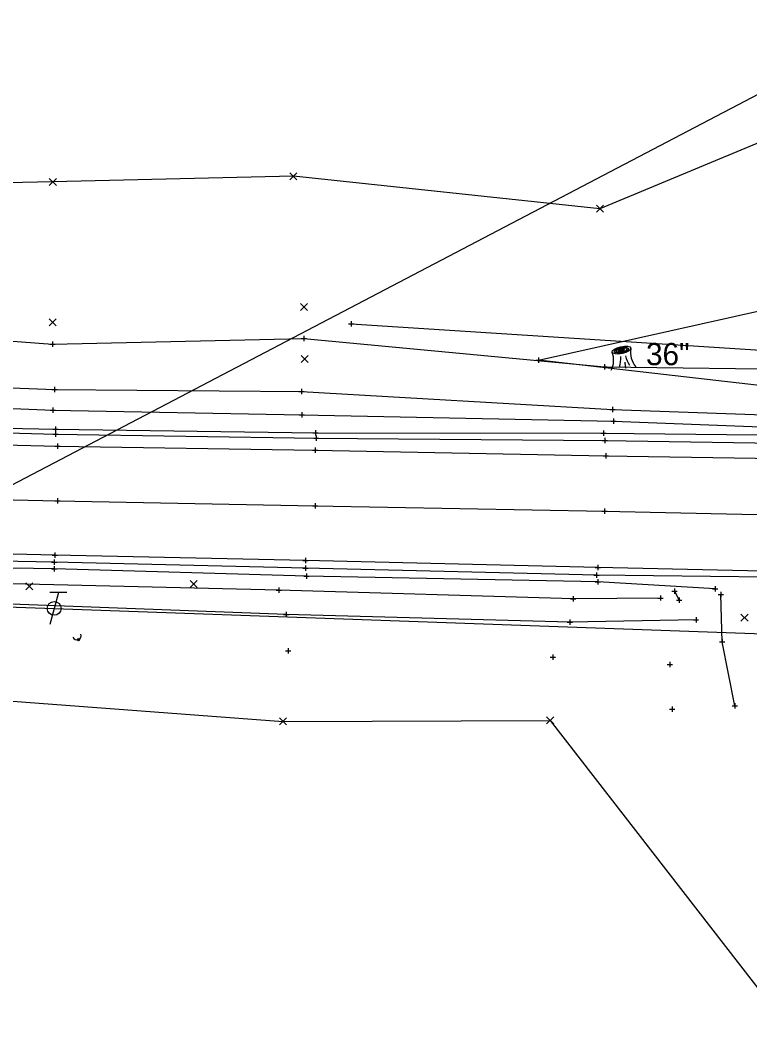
# Model space of a CAD drawing. Extents: x 2005176 to 2005823, y 572472 to 572942.
# Drawn here: x 2005315.2 to 2005452.2, y 572515.6 to 572703.5 of the extents above; entities that cross this region are included whole.
import ezdxf

# ---------------------------------------------------------------- set-up
doc = ezdxf.new("R2010")
doc.units = 0
for name, color, linetype in [('DV_X_Lot_Line', 7, 'Continuous'), ('GE_X_Alignment_1000_Bearings', 7, 'Continuous'), ('GE_X_Alignment_1000_Cardinal_Points', 7, 'Continuous'), ('GE_X_Alignment_100_Bearings', 7, 'Continuous'), ('GE_X_Alignment_100_Cardinal_Points', 7, 'Continuous'), ('GE_X_Alignment_100_Curve_Data', 7, 'Continuous'), ('GE_X_Alignment_100_Distances', 7, 'Continuous'), ('GE_X_Alignment_100_Stations', 7, 'Continuous'), ('GE_X_Alignment_500_Bearings', 7, 'Continuous'), ('GE_X_Alignment_500_Cardinal_Points', 7, 'Continuous'), ('GE_X_Alignment_500_Distances', 7, 'Continuous'), ('SC_Scratch1', 7, 'Continuous'), ('SC_Scratch10', 7, 'Continuous'), ('SC_Scratch8', 7, 'Continuous'), ('SV_P_Mon_Cells_Set', 7, 'Continuous'), ('SV_X_Random_Point', 7, 'Continuous'), ('SV_X_Shot_Marker', 7, 'Continuous'), ('SV_X_Terrain_Boundary', 7, 'Continuous'), ('UT_X_Overhead_Electric', 7, 'Continuous'), ('UT_X_Overhead_Telecom', 7, 'Continuous'), ('VG_X_Text', 7, 'Continuous')]:
    doc.layers.add(name, color=color, linetype=linetype)

msp = doc.modelspace()

# ---------------------------------------------------------------- linework, layer by layer
at = {"layer": 'DV_X_Lot_Line'}
msp.add_circle((2005326.15, 572587.14), 0.2, dxfattribs=at)
msp.add_arc((2005325.87, 572587.89), 0.8, 200, 20, dxfattribs=at)
at = {"layer": 'GE_X_Alignment_1000_Bearings'}
msp.add_lwpolyline([(2005377.36, 572646.47), (2005740.51, 572623.1)], dxfattribs=at)
at = {"layer": 'GE_X_Alignment_1000_Cardinal_Points'}
msp.add_lwpolyline([(2005589.36, 572669.58), (2005577.83, 572653.68), (2005542.16, 572637.38), (2005475.27, 572632.41), (2005412.5, 572639.63), (2005455.37, 572649.17), (2005453.82, 572664.21)], dxfattribs=at)
at = {"layer": 'GE_X_Alignment_100_Bearings'}
for points in [[(2005220.7, 572626.42), (2005272.19, 572624.71), (2005322.24, 572623.5), (2005370.59, 572622.7), (2005425.14, 572621.65), (2005477.36, 572620.84), (2005525.07, 572619.6), (2005576.7, 572617.86), (2005628.14, 572615.99), (2005678.39, 572614.09), (2005728.23, 572612.03), (2005777.04, 572611.02), (2005819.95, 572609.99)], [(2005818.64, 572588.97), (2005775.2, 572590.4), (2005728.29, 572591.88), (2005676.68, 572593.61), (2005626.55, 572595.19), (2005577.83, 572596.72), (2005526.97, 572598.44), (2005477.01, 572599.53), (2005423.67, 572600.7), (2005368.75, 572601.99), (2005321.74, 572602.99), (2005266.72, 572604.35), (2005220.03, 572605.66)]]:
    msp.add_lwpolyline(points, dxfattribs=at)
at = {"layer": 'GE_X_Alignment_100_Cardinal_Points'}
msp.add_lwpolyline([(2005220.5, 572615.99), (2005272.51, 572614.37), (2005322.2, 572613.2), (2005370.62, 572612.29), (2005424.94, 572611.27), (2005476.5, 572610.17), (2005524.32, 572608.79), (2005576.49, 572607.4), (2005627.69, 572605.77), (2005677.11, 572603.68), (2005728.03, 572601.92), (2005776.18, 572600.5), (2005820.14, 572599.28)], dxfattribs=at)
at = {"layer": 'GE_X_Alignment_100_Curve_Data'}
msp.add_lwpolyline([(2005449.4, 572574.75), (2005447.03, 572586.75), (2005446.73, 572595.6)], dxfattribs=at)
at = {"layer": 'GE_X_Alignment_100_Distances'}
for points in [[(2005220.68, 572626.38), (2005272.19, 572624.71), (2005322.24, 572623.5), (2005370.59, 572622.7), (2005425.14, 572621.65), (2005477.36, 572620.84), (2005525.07, 572619.6), (2005576.7, 572617.86), (2005628.14, 572615.99), (2005678.39, 572614.09), (2005728.23, 572612.03), (2005777.04, 572611.02), (2005820.02, 572609.9)], [(2005818.7, 572589.05), (2005775.2, 572590.4), (2005728.29, 572591.88), (2005676.68, 572593.61), (2005626.55, 572595.19), (2005577.83, 572596.72), (2005526.97, 572598.44), (2005477.01, 572599.53), (2005423.67, 572600.7), (2005368.75, 572601.99), (2005321.74, 572602.99), (2005266.72, 572604.35), (2005220.06, 572605.65)]]:
    msp.add_lwpolyline(points, dxfattribs=at)
at = {"layer": 'GE_X_Alignment_100_Stations'}
for points in [[(2005222.43, 572636.47), (2005271.73, 572636.06), (2005321.63, 572634.11), (2005368.05, 572633.72), (2005426.44, 572630.35), (2005456.6, 572629.27), (2005476.49, 572629.52), (2005493.02, 572629.48), (2005502.46, 572637.33)], [(2005435.44, 572594.97), (2005419.01, 572594.84), (2005363.8, 572596.44), (2005313.6, 572597.65), (2005274.17, 572598.2), (2005257.36, 572598.58), (2005234.71, 572598.81)]]:
    msp.add_lwpolyline(points, dxfattribs=at)
at = {"layer": 'GE_X_Alignment_500_Bearings'}
for points in [[(2005221.46, 572633.88), (2005271.77, 572632.29), (2005321.33, 572630.21), (2005368.11, 572629.36), (2005426.58, 572628.14), (2005455.88, 572627.02), (2005475.7, 572627.77)], [(2005438.04, 572596.23), (2005438.95, 572594.56)]]:
    msp.add_lwpolyline(points, dxfattribs=at)
at = {"layer": 'GE_X_Alignment_500_Cardinal_Points'}
for points in [[(2005223.7, 572649.48), (2005272.16, 572646.31), (2005321.29, 572642.61), (2005368.45, 572643.7), (2005424.94, 572638.4), (2005464.26, 572637.84), (2005477.31, 572636.75), (2005486.33, 572634.29), (2005489.17, 572649.33), (2005492.03, 572660.48), (2005500.98, 572662.63), (2005517.14, 572685.76), (2005532.69, 572703.48)], [(2005442.09, 572590.88), (2005418.43, 572590.46), (2005365.12, 572591.87), (2005313.53, 572593.79), (2005275.04, 572595.23), (2005256.78, 572594), (2005241.01, 572592.26)]]:
    msp.add_lwpolyline(points, dxfattribs=at)
at = {"layer": 'GE_X_Alignment_500_Distances'}
msp.add_lwpolyline([(2005220.4, 572616.04), (2005272.51, 572614.37), (2005322.2, 572613.2), (2005370.62, 572612.29), (2005424.94, 572611.27), (2005476.5, 572610.17), (2005524.32, 572608.79), (2005576.49, 572607.4), (2005627.69, 572605.77), (2005677.11, 572603.68), (2005728.03, 572601.92), (2005776.18, 572600.5), (2005820.14, 572599.26)], dxfattribs=at)
at = {"layer": 'SC_Scratch1'}
for p, q in [((2005322.4, 572596.02), (2005320.79, 572590.02)), ((2005324, 572596.02), (2005320.8, 572596.02))]:
    msp.add_line(p, q, dxfattribs=at)
msp.add_circle((2005321.6, 572593.02), 1.3, dxfattribs=at)
at = {"layer": 'SC_Scratch10'}
for points in [[(2005220.88, 572629.15), (2005272.14, 572627.64), (2005321.83, 572626.68), (2005370.65, 572626), (2005424.7, 572625.92), (2005476.69, 572625.33), (2005525.49, 572622.56), (2005576.48, 572620.99), (2005628.3, 572618.68), (2005678.32, 572615.98), (2005728.35, 572614.83)], [(2005445.69, 572596.69), (2005423.63, 572598.01), (2005368.95, 572599.06), (2005321.59, 572600.44), (2005267.14, 572601.3), (2005220.21, 572602.17)]]:
    msp.add_lwpolyline(points, dxfattribs=at)
at = {"layer": 'SC_Scratch8'}
for points in [[(2005220.9, 572628.72), (2005272.16, 572627.13), (2005321.83, 572625.74), (2005370.81, 572625), (2005424.98, 572624.56), (2005477.31, 572623.7), (2005525.21, 572621.63), (2005576.56, 572620.01), (2005628.24, 572617.89), (2005678.25, 572615.23), (2005728.27, 572613.25), (2005777.12, 572612.24), (2005820.02, 572611.5)], [(2005818.66, 572586.64), (2005775.01, 572588.28), (2005728.16, 572589.79), (2005676.75, 572591.58), (2005626.73, 572593.57), (2005577.92, 572595.76), (2005527.42, 572597.32), (2005476.91, 572598.65), (2005423.43, 572599.27), (2005368.77, 572600.6), (2005321.59, 572601.67), (2005267.03, 572602.73), (2005220.03, 572603.93)]]:
    msp.add_lwpolyline(points, dxfattribs=at)
at = {"layer": 'SV_P_Mon_Cells_Set'}
for p, q in [((2005376.86, 572646.47), (2005377.86, 572646.47)), ((2005377.36, 572646.97), (2005377.36, 572645.97)), ((2005377.36, 572646.47), (2005377.36, 572646.47)), ((2005368.45, 572644.2), (2005368.45, 572643.2)), ((2005320.79, 572642.61), (2005321.79, 572642.61)), ((2005321.29, 572643.11), (2005321.29, 572642.11)), ((2005321.29, 572642.61), (2005321.29, 572642.61)), ((2005367.95, 572643.7), (2005368.95, 572643.7)), ((2005368.45, 572643.7), (2005368.45, 572643.7)), ((2005412, 572639.63), (2005413, 572639.63)), ((2005412.5, 572640.13), (2005412.5, 572639.13)), ((2005412.5, 572639.63), (2005412.5, 572639.63)), ((2005424.44, 572638.4), (2005425.44, 572638.4)), ((2005424.94, 572638.9), (2005424.94, 572637.9)), ((2005424.94, 572638.4), (2005424.94, 572638.4)), ((2005321.63, 572634.61), (2005321.63, 572633.61)), ((2005321.13, 572634.11), (2005322.13, 572634.11)), ((2005321.63, 572634.11), (2005321.63, 572634.11)), ((2005367.55, 572633.72), (2005368.55, 572633.72)), ((2005368.05, 572634.22), (2005368.05, 572633.22)), ((2005368.05, 572633.72), (2005368.05, 572633.72)), ((2005426.44, 572630.85), (2005426.44, 572629.85)), ((2005320.83, 572630.21), (2005321.83, 572630.21)), ((2005321.33, 572630.71), (2005321.33, 572629.71)), ((2005321.33, 572630.21), (2005321.33, 572630.21)), ((2005367.61, 572629.36), (2005368.61, 572629.36)), ((2005368.11, 572629.86), (2005368.11, 572628.86)), ((2005368.11, 572629.36), (2005368.11, 572629.36)), ((2005425.94, 572630.35), (2005426.94, 572630.35)), ((2005426.44, 572630.35), (2005426.44, 572630.35)), ((2005321.83, 572627.18), (2005321.83, 572626.18)), ((2005426.08, 572628.14), (2005427.08, 572628.14)), ((2005426.58, 572628.64), (2005426.58, 572627.64)), ((2005426.58, 572628.14), (2005426.58, 572628.14)), ((2005321.33, 572626.68), (2005322.33, 572626.68)), ((2005321.33, 572625.74), (2005322.33, 572625.74)), ((2005321.83, 572626.68), (2005321.83, 572626.68)), ((2005321.83, 572626.24), (2005321.83, 572625.24)), ((2005321.83, 572625.74), (2005321.83, 572625.74)), ((2005370.15, 572626), (2005371.15, 572626)), ((2005370.65, 572626.5), (2005370.65, 572625.5)), ((2005370.65, 572626), (2005370.65, 572626)), ((2005370.81, 572625.5), (2005370.81, 572624.5)), ((2005424.2, 572625.92), (2005425.2, 572625.92)), ((2005424.7, 572626.42), (2005424.7, 572625.42)), ((2005424.7, 572625.92), (2005424.7, 572625.92)), ((2005321.74, 572623.5), (2005322.74, 572623.5)), ((2005321.74, 572623.5), (2005322.74, 572623.5)), ((2005322.24, 572624), (2005322.24, 572623)), ((2005322.24, 572624), (2005322.24, 572623)), ((2005322.24, 572623.5), (2005322.24, 572623.5)), ((2005322.24, 572623.5), (2005322.24, 572623.5)), ((2005370.31, 572625), (2005371.31, 572625)), ((2005370.81, 572625), (2005370.81, 572625)), ((2005424.48, 572624.56), (2005425.48, 572624.56)), ((2005424.98, 572625.06), (2005424.98, 572624.06)), ((2005424.98, 572624.56), (2005424.98, 572624.56)), ((2005370.09, 572622.7), (2005371.09, 572622.7)), ((2005370.09, 572622.7), (2005371.09, 572622.7)), ((2005370.59, 572623.2), (2005370.59, 572622.2)), ((2005370.59, 572623.2), (2005370.59, 572622.2)), ((2005370.59, 572622.7), (2005370.59, 572622.7)), ((2005370.59, 572622.7), (2005370.59, 572622.7)), ((2005424.64, 572621.65), (2005425.64, 572621.65)), ((2005424.64, 572621.65), (2005425.64, 572621.65)), ((2005425.14, 572622.15), (2005425.14, 572621.15)), ((2005425.14, 572622.15), (2005425.14, 572621.15)), ((2005425.14, 572621.65), (2005425.14, 572621.65)), ((2005425.14, 572621.65), (2005425.14, 572621.65)), ((2005321.7, 572613.2), (2005322.7, 572613.2)), ((2005321.7, 572613.2), (2005322.7, 572613.2)), ((2005322.2, 572613.7), (2005322.2, 572612.7)), ((2005322.2, 572613.7), (2005322.2, 572612.7)), ((2005322.2, 572613.2), (2005322.2, 572613.2)), ((2005322.2, 572613.2), (2005322.2, 572613.2)), ((2005370.12, 572612.29), (2005371.12, 572612.29)), ((2005370.12, 572612.29), (2005371.12, 572612.29)), ((2005370.62, 572612.79), (2005370.62, 572611.79)), ((2005370.62, 572612.79), (2005370.62, 572611.79)), ((2005370.62, 572612.29), (2005370.62, 572612.29)), ((2005370.62, 572612.29), (2005370.62, 572612.29)), ((2005424.44, 572611.27), (2005425.44, 572611.27)), ((2005424.44, 572611.27), (2005425.44, 572611.27)), ((2005424.94, 572611.77), (2005424.94, 572610.77)), ((2005424.94, 572611.77), (2005424.94, 572610.77)), ((2005424.94, 572611.27), (2005424.94, 572611.27)), ((2005424.94, 572611.27), (2005424.94, 572611.27)), ((2005321.24, 572602.99), (2005322.24, 572602.99)), ((2005321.24, 572602.99), (2005322.24, 572602.99)), ((2005321.74, 572603.49), (2005321.74, 572602.49)), ((2005321.74, 572603.49), (2005321.74, 572602.49)), ((2005321.74, 572602.99), (2005321.74, 572602.99)), ((2005321.74, 572602.99), (2005321.74, 572602.99)), ((2005321.09, 572601.67), (2005322.09, 572601.67)), ((2005321.59, 572602.17), (2005321.59, 572601.17)), ((2005321.59, 572601.67), (2005321.59, 572601.67)), ((2005321.59, 572600.94), (2005321.59, 572599.94)), ((2005368.25, 572601.99), (2005369.25, 572601.99)), ((2005368.25, 572601.99), (2005369.25, 572601.99)), ((2005368.75, 572602.49), (2005368.75, 572601.49)), ((2005368.75, 572602.49), (2005368.75, 572601.49)), ((2005368.75, 572601.99), (2005368.75, 572601.99)), ((2005368.75, 572601.99), (2005368.75, 572601.99)), ((2005368.77, 572601.1), (2005368.77, 572600.1)), ((2005423.67, 572601.2), (2005423.67, 572600.2)), ((2005423.67, 572601.2), (2005423.67, 572600.2)), ((2005321.09, 572600.44), (2005322.09, 572600.44)), ((2005321.59, 572600.44), (2005321.59, 572600.44)), ((2005368.27, 572600.6), (2005369.27, 572600.6)), ((2005368.45, 572599.06), (2005369.45, 572599.06)), ((2005368.77, 572600.6), (2005368.77, 572600.6)), ((2005368.95, 572599.56), (2005368.95, 572598.56)), ((2005368.95, 572599.06), (2005368.95, 572599.06)), ((2005422.93, 572599.27), (2005423.93, 572599.27)), ((2005423.17, 572600.7), (2005424.17, 572600.7)), ((2005423.17, 572600.7), (2005424.17, 572600.7)), ((2005423.43, 572599.77), (2005423.43, 572598.77)), ((2005423.43, 572599.27), (2005423.43, 572599.27)), ((2005423.67, 572600.7), (2005423.67, 572600.7)), ((2005423.67, 572600.7), (2005423.67, 572600.7)), ((2005423.13, 572598.01), (2005424.13, 572598.01)), ((2005423.63, 572598.51), (2005423.63, 572597.51)), ((2005423.63, 572598.01), (2005423.63, 572598.01)), ((2005445.69, 572597.19), (2005445.69, 572596.19)), ((2005363.3, 572596.44), (2005364.3, 572596.44)), ((2005363.8, 572596.94), (2005363.8, 572595.94)), ((2005363.8, 572596.44), (2005363.8, 572596.44)), ((2005419.01, 572595.34), (2005419.01, 572594.34)), ((2005435.44, 572595.47), (2005435.44, 572594.47)), ((2005437.54, 572596.23), (2005438.54, 572596.23)), ((2005438.04, 572596.73), (2005438.04, 572595.73)), ((2005438.04, 572596.23), (2005438.04, 572596.23)), ((2005445.19, 572596.69), (2005446.19, 572596.69)), ((2005445.69, 572596.69), (2005445.69, 572596.69)), ((2005446.23, 572595.6), (2005447.23, 572595.6)), ((2005446.73, 572596.1), (2005446.73, 572595.1)), ((2005446.73, 572595.6), (2005446.73, 572595.6)), ((2005418.51, 572594.84), (2005419.51, 572594.84)), ((2005419.01, 572594.84), (2005419.01, 572594.84)), ((2005434.94, 572594.97), (2005435.94, 572594.97)), ((2005435.44, 572594.97), (2005435.44, 572594.97)), ((2005438.45, 572594.56), (2005439.45, 572594.56)), ((2005438.95, 572595.06), (2005438.95, 572594.06)), ((2005438.95, 572594.56), (2005438.95, 572594.56)), ((2005364.62, 572591.87), (2005365.62, 572591.87)), ((2005365.12, 572592.37), (2005365.12, 572591.37)), ((2005365.12, 572591.87), (2005365.12, 572591.87)), ((2005442.09, 572591.38), (2005442.09, 572590.38)), ((2005417.93, 572590.46), (2005418.93, 572590.46)), ((2005418.43, 572590.96), (2005418.43, 572589.96)), ((2005418.43, 572590.46), (2005418.43, 572590.46)), ((2005441.59, 572590.88), (2005442.59, 572590.88)), ((2005442.09, 572590.88), (2005442.09, 572590.88)), ((2005446.53, 572586.75), (2005447.53, 572586.75)), ((2005447.03, 572587.25), (2005447.03, 572586.25)), ((2005447.03, 572586.75), (2005447.03, 572586.75)), ((2005365.04, 572585.07), (2005366.04, 572585.07)), ((2005365.54, 572585.57), (2005365.54, 572584.57)), ((2005365.54, 572585.07), (2005365.54, 572585.07)), ((2005414.72, 572583.89), (2005415.72, 572583.89)), ((2005415.22, 572584.39), (2005415.22, 572583.39)), ((2005415.22, 572583.89), (2005415.22, 572583.89)), ((2005436.65, 572582.46), (2005437.65, 572582.46)), ((2005437.15, 572582.96), (2005437.15, 572581.96)), ((2005437.15, 572582.46), (2005437.15, 572582.46)), ((2005437.62, 572574.57), (2005437.62, 572573.57)), ((2005448.9, 572574.75), (2005449.9, 572574.75)), ((2005449.4, 572575.25), (2005449.4, 572574.25)), ((2005449.4, 572574.75), (2005449.4, 572574.75)), ((2005437.12, 572574.07), (2005438.12, 572574.07)), ((2005437.62, 572574.07), (2005437.62, 572574.07))]:
    msp.add_line(p, q, dxfattribs=at)
at = {"layer": 'SV_X_Random_Point'}
for p, q in [((2005365.84, 572673.48), (2005367.18, 572674.82)), ((2005365.84, 572674.82), (2005367.18, 572673.48)), ((2005320.67, 572672.42), (2005322, 572673.76)), ((2005320.67, 572673.76), (2005322, 572672.42)), ((2005423.39, 572667.4), (2005424.72, 572668.73)), ((2005423.39, 572668.73), (2005424.72, 572667.4)), ((2005367.85, 572648.93), (2005369.18, 572650.26)), ((2005367.85, 572650.26), (2005369.18, 572648.93)), ((2005320.63, 572646.07), (2005321.97, 572647.4)), ((2005320.63, 572647.4), (2005321.97, 572646.07)), ((2005367.97, 572639.18), (2005369.3, 572640.52)), ((2005367.97, 572640.52), (2005369.3, 572639.18)), ((2005316.26, 572596.5), (2005317.59, 572597.83)), ((2005316.26, 572597.83), (2005317.59, 572596.5)), ((2005347.13, 572596.94), (2005348.46, 572598.28)), ((2005347.13, 572598.28), (2005348.46, 572596.94)), ((2005450.53, 572590.61), (2005451.86, 572591.95)), ((2005450.53, 572591.95), (2005451.86, 572590.61)), ((2005414.04, 572571.33), (2005415.37, 572572.66)), ((2005414.04, 572572.66), (2005415.37, 572571.33)), ((2005363.9, 572571.14), (2005365.24, 572572.48)), ((2005363.9, 572572.48), (2005365.24, 572571.14))]:
    msp.add_line(p, q, dxfattribs=at)
at = {"layer": 'SV_X_Shot_Marker'}
msp.add_line((2005428.46, 572639.99), (2005428.46, 572639.99), dxfattribs=at)
for centre, radius, start, end in [((2005422.63, 572639.65), 4, 331.5338, 20.9269), ((2005422.94, 572640.02), 5.05, 340.7938, 3.5481), ((2005434.97, 572642.05), 6.32, 194.9653, 212.1216), ((2005434.07, 572641.14), 4.29, 171.4106, 219.9194), ((2005432.37, 572639.19), 3.64, 178.7926, 197.1224)]:
    msp.add_arc(centre, radius, start, end, dxfattribs=at)
for major_axis in [(1.74, 0.37), (1.3, 0.28), (0.976, 0.211), (0.549, 0.119), (0.309, 0.067)]:
    msp.add_ellipse((2005428.09, 572641.51), major_axis=major_axis, ratio=0.36865, dxfattribs=at)
at = {"layer": 'SV_X_Terrain_Boundary'}
for points in [[(2005481.51, 572691.94), (2005424.05, 572668.06), (2005366.51, 572674.15), (2005321.34, 572673.09), (2005272.77, 572672.06), (2005221.81, 572669.25), (2005223.7, 572649.48), (2005222.43, 572636.47), (2005221.46, 572633.88), (2005220.9, 572628.72), (2005220.68, 572626.38), (2005220.5, 572615.99), (2005220.5, 572615.99), (2005220.4, 572616.04), (2005220.03, 572605.66), (2005220.03, 572603.93), (2005220.21, 572602.17), (2005219.97, 572596.9)], [(2005219.97, 572596.9), (2005227.07, 572580.24), (2005274.02, 572576.73), (2005310.42, 572575.86), (2005364.57, 572571.81), (2005414.7, 572571.99), (2005458.48, 572515.56)]]:
    msp.add_lwpolyline(points, dxfattribs=at)
at = {"layer": 'UT_X_Overhead_Electric'}
msp.add_line((2005235.79, 572575.46), (2005462.76, 572694.31), dxfattribs=at)
at = {"layer": 'UT_X_Overhead_Telecom'}
for p, q in [((2005177.67, 572598.21), (2005321.6, 572593.02)), ((2005321.6, 572593.02), (2005468.84, 572587.72))]:
    msp.add_line(p, q, dxfattribs=at)

# ---------------------------------------------------------------- texts
at = {"layer": 'VG_X_Text'}
msp.add_text('36"', height=4.167, dxfattribs=at).set_placement((2005432.71, 572638.68))

doc.saveas('drawing.dxf')
